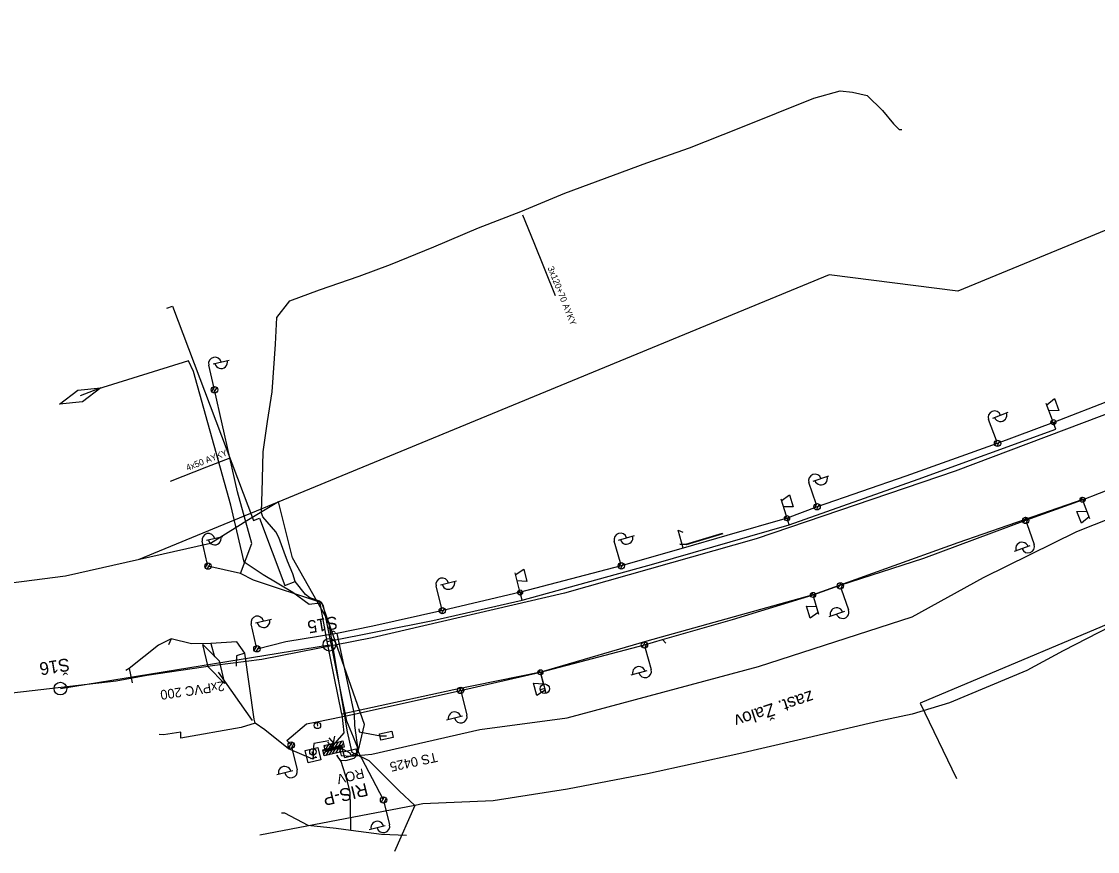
# Model space of a CAD drawing. Extents: x -748507 to -687366, y -1057342 to -1024924.
# Drawn here: x -745681.2 to -745512.4, y -1033626.6 to -1033496.4 of the extents above; entities that cross this region are included whole.
import ezdxf

# ---------------------------------------------------------------- set-up
doc = ezdxf.new("R2010")
doc.units = 0
for name, color, linetype in [('6kV - SŽDC', 7, 'Continuous'), ('DK + TKK - SŽDC', 7, 'Continuous'), ('DK - Pha Holešovice - Kralupy - ČD TELEMATIKA', 7, 'Continuous'), ('kanalizace ČD', 7, 'Continuous'), ('PRE - NN', 7, 'Continuous'), ('Sděl MK - SŽDC', 7, 'Continuous'), ('Telefonica O2', 7, 'Continuous'), ('TK+DOK_Pha Holešovice - Kralupy', 7, 'Continuous'), ('Vedení NN - SŽDC', 7, 'Continuous'), ('Vrstva 14', 7, 'Continuous')]:
    doc.layers.add(name, color=color, linetype=linetype)

msp = doc.modelspace()

# ---------------------------------------------------------------- linework, layer by layer
at = {"layer": '6kV - SŽDC'}
msp.add_lwpolyline([(-745623.06, -1033607.71), (-745622.85, -1033608.69), (-745624.8, -1033609.11), (-745625.01, -1033608.13), (-745623.06, -1033607.71)], dxfattribs=at)
at = {"layer": 'DK + TKK - SŽDC'}
for p, q in [((-745635.5, -1033610.94), (-745635.4, -1033610.94)), ((-745635.45, -1033610.94), (-745635.35, -1033611.47))]:
    msp.add_line(p, q, dxfattribs=at)
for points in [[(-745400.08, -1033513.57), (-745427.68, -1033524.27), (-745452.16, -1033534.47), (-745459.47, -1033537.75), (-745479.21, -1033545.61), (-745485.05, -1033547.78), (-745506.18, -1033556.13), (-745534.69, -1033566.93), (-745565.92, -1033577.52), (-745596.01, -1033586.03), (-745626.14, -1033593.03), (-745643.48, -1033596.47), (-745650.81, -1033597.4), (-745661.52, -1033598.96), (-745666.31, -1033599.86), (-745684.01, -1033601.91)], [(-745646.14, -1033595.44), (-745647.37, -1033593.68), (-745651.44, -1033593.92), (-745654.47, -1033593.99), (-745657.67, -1033593.23), (-745659.67, -1033594.21), (-745664.26, -1033597.87), (-745664.79, -1033598.17)], [(-745657.67, -1033593.23), (-745658.09, -1033594.14)], [(-745651.44, -1033593.92), (-745650.87, -1033596.04)], [(-745647.42, -1033595.9), (-745647.5, -1033597.52)], [(-745646.14, -1033595.44), (-745647.42, -1033595.9)], [(-745644.52, -1033606.43), (-745644.64, -1033605.81), (-745646.14, -1033595.44)], [(-745664.26, -1033597.87), (-745663.78, -1033600.09)], [(-745635.46, -1033612.08), (-745639.27, -1033610.46), (-745643, -1033607.49), (-745644.52, -1033606.43), (-745646.7, -1033607.11), (-745656.14, -1033608.79), (-745656.17, -1033607.85), (-745658.89, -1033608.26), (-745659.58, -1033608.2)], [(-745635.35, -1033611.47), (-745635.46, -1033612.08), (-745634.97, -1033611.67)]]:
    msp.add_lwpolyline(points, dxfattribs=at)
msp.add_circle((-745635.45, -1033610.94), 0.5, dxfattribs=at)
at = {"layer": 'DK - Pha Holešovice - Kralupy - ČD TELEMATIKA'}
msp.add_lwpolyline([(-745431.67, -1033496.38), (-745534.27, -1033538.65), (-745554.49, -1033536.11), (-745662.86, -1033580.81)], dxfattribs=at)
at = {"layer": 'kanalizace ČD'}
for p, q in [((-745576.95, -1033578.35), (-745571.2, -1033576.65)), ((-745577.91, -1033578.29), (-745576.95, -1033578.35))]:
    msp.add_line(p, q, dxfattribs=at)
for points in [[(-745571.15, -1033576.76), (-745576.92, -1033578.47), (-745577.91, -1033578.41)], [(-745675.05, -1033601.01), (-745632.86, -1033594.14)]]:
    msp.add_lwpolyline(points, dxfattribs=at)
for centre in [(-745632.86, -1033594.14), (-745675.05, -1033601.01)]:
    msp.add_circle(centre, 1, dxfattribs=at)
at = {"layer": 'PRE - NN'}
for points in [[(-745638.23, -1033584.22), (-745638.24, -1033584.21), (-745638.58, -1033583), (-745639.44, -1033581.03), (-745639.96, -1033579.64), (-745640.79, -1033577.29), (-745641.28, -1033576.41), (-745643.29, -1033574.08), (-745643.49, -1033573.45), (-745643.44, -1033571.53), (-745643.4, -1033570.21), (-745643.24, -1033563.88), (-745642.59, -1033559.13), (-745641.83, -1033554.45), (-745641.32, -1033547.01), (-745641.13, -1033542.81), (-745639.06, -1033540.19), (-745634.41, -1033538.48), (-745628.2, -1033536.34), (-745623.3, -1033534.49), (-745616.47, -1033531.74), (-745609.47, -1033528.73), (-745602.84, -1033526.2), (-745595.91, -1033523.32), (-745588.31, -1033520.48), (-745583.08, -1033518.55), (-745576.4, -1033516.2), (-745568.58, -1033513.09), (-745556.86, -1033508.39), (-745552.77, -1033507.23), (-745550.83, -1033507.45), (-745548.5, -1033507.97), (-745546.13, -1033510.35), (-745544.39, -1033512.43), (-745543.52, -1033513.33), (-745543.1, -1033513.31)], [(-745602.59, -1033526.68), (-745600.79, -1033531.05), (-745597.46, -1033539.34)], [(-745658.36, -1033541.35), (-745657.46, -1033541.01), (-745644.77, -1033574.64), (-745643.83, -1033574.28), (-745639.85, -1033584.82), (-745638.24, -1033584.21)], [(-745657.81, -1033568.48), (-745652.08, -1033566.23), (-745648.44, -1033564.84)], [(-745631.64, -1033611.45), (-745631.49, -1033611.85), (-745631.13, -1033612.23), (-745630.29, -1033612.31), (-745628.98, -1033611.93), (-745628.73, -1033611.66), (-745628.5, -1033611.07), (-745628.46, -1033610.2), (-745629.07, -1033608.61), (-745630.13, -1033606.11), (-745633.81, -1033588.02), (-745634.11, -1033587.54), (-745634.41, -1033587.32), (-745635.93, -1033586.8), (-745636.62, -1033586.24), (-745638.23, -1033584.22)], [(-745629.52, -1033623.21), (-745629.49, -1033622.95), (-745629.56, -1033619.43), (-745629.6, -1033617.29), (-745630.02, -1033615.6), (-745631.01, -1033612.45), (-745631.72, -1033611.45)], [(-745640.4, -1033620.51), (-745639.9, -1033620.52), (-745636.24, -1033622.42), (-745631.78, -1033622.93), (-745629.52, -1033623.21)], [(-745629.52, -1033623.21), (-745624.71, -1033623.85), (-745620.75, -1033624.02)]]:
    msp.add_lwpolyline(points, dxfattribs=at)
at = {"layer": 'Sděl MK - SŽDC'}
for p, q in [((-745520.36, -1033556.52), (-745519.14, -1033555.53)), ((-745519.14, -1033555.53), (-745518.43, -1033557.4)), ((-745520.47, -1033556.24), (-745519.48, -1033558.86)), ((-745518.43, -1033557.4), (-745520.01, -1033557.46)), ((-745519.64, -1033559.46), (-745519.35, -1033558.83)), ((-745519.27, -1033559.62), (-745518.99, -1033559)), ((-745562.08, -1033571.25), (-745561.23, -1033573.92)), ((-745561.98, -1033571.54), (-745560.7, -1033570.61)), ((-745560.7, -1033570.61), (-745560.1, -1033572.52)), ((-745514.78, -1033571), (-745515.06, -1033571.62)), ((-745514.41, -1033571.16), (-745514.7, -1033571.79)), ((-745560.1, -1033572.52), (-745561.69, -1033572.49)), ((-745513.57, -1033574.37), (-745514.57, -1033571.76)), ((-745561.42, -1033574.51), (-745561.1, -1033573.89)), ((-745561.07, -1033574.69), (-745560.75, -1033574.08)), ((-745515.61, -1033573.22), (-745514.03, -1033573.16)), ((-745514.9, -1033575.09), (-745515.61, -1033573.22)), ((-745513.68, -1033574.09), (-745514.9, -1033575.09)), ((-745603.79, -1033582.86), (-745603.08, -1033585.56)), ((-745603.71, -1033583.15), (-745602.39, -1033582.28)), ((-745602.39, -1033582.28), (-745601.88, -1033584.22)), ((-745601.88, -1033584.22), (-745603.46, -1033584.12)), ((-745603.29, -1033586.15), (-745602.94, -1033585.55)), ((-745602.94, -1033586.34), (-745602.6, -1033585.75)), ((-745557.03, -1033585.92), (-745557.36, -1033586.52)), ((-745556.67, -1033586.11), (-745557.01, -1033586.72)), ((-745557.47, -1033589.99), (-745558.04, -1033588.07)), ((-745558.04, -1033588.07), (-745556.45, -1033588.13)), ((-745556.09, -1033589.38), (-745556.88, -1033586.7)), ((-745556.18, -1033589.09), (-745557.47, -1033589.99)), ((-745599.78, -1033598.05), (-745600.12, -1033598.64)), ((-745599.43, -1033598.25), (-745599.78, -1033598.85)), ((-745598.93, -1033601.54), (-745599.65, -1033598.83)), ((-745600.33, -1033602.11), (-745600.84, -1033600.18)), ((-745600.84, -1033600.18), (-745599.26, -1033600.28)), ((-745599.01, -1033601.25), (-745600.33, -1033602.11)), ((-745632.36, -1033611.27), (-745631.63, -1033610.06)), ((-745631.85, -1033611.14), (-745631.11, -1033609.93)), ((-745635.32, -1033611.93), (-745635.56, -1033610.96)), ((-745633.85, -1033610.82), (-745633.69, -1033610.56)), ((-745633.72, -1033611.34), (-745633.17, -1033610.43)), ((-745633.39, -1033611.52), (-745632.66, -1033610.31)), ((-745632.88, -1033611.39), (-745632.14, -1033610.18)), ((-745631.33, -1033611.02), (-745630.89, -1033610.29)), ((-745630.82, -1033610.89), (-745630.77, -1033610.81)), ((-745634.84, -1033611.82), (-745635.81, -1033612.05))]:
    msp.add_line(p, q, dxfattribs=at)
for points in [[(-745633.23, -1033593.61), (-745634.32, -1033587.61), (-745636.06, -1033587.84), (-745638.61, -1033585.93), (-745643.25, -1033583.15), (-745646.23, -1033581.17), (-745648.31, -1033572.26), (-745654.16, -1033551.3), (-745654.98, -1033549.58), (-745669.24, -1033554.03), (-745671.95, -1033555.11)], [(-745668.7, -1033553.82), (-745671.58, -1033556.04), (-745675.2, -1033556.41), (-745672.33, -1033554.18), (-745668.7, -1033553.82)], [(-745518.94, -1033560.3), (-745519.32, -1033559.21)], [(-745630.92, -1033605.02), (-745632.09, -1033599.11), (-745633.23, -1033593.61), (-745616.65, -1033590.34), (-745602.63, -1033587.13), (-745581.95, -1033581.43), (-745560.76, -1033575.32), (-745540.52, -1033568.15), (-745518.94, -1033560.3)], [(-745514.7, -1033571.37), (-745534.28, -1033578.14), (-745556.98, -1033586.32), (-745583.06, -1033593.6), (-745599.72, -1033598.43), (-745613.34, -1033601.2), (-745630.92, -1033605.02), (-745630.61, -1033607.96), (-745632.67, -1033610.37)], [(-745560.76, -1033575.32), (-745561.07, -1033574.26)], [(-745602.63, -1033587.13), (-745602.93, -1033585.92)], [(-745652.7, -1033594.08), (-745650.13, -1033596.65), (-745649.3, -1033600.19), (-745651.87, -1033597.62), (-745652.7, -1033594.08)], [(-745644.92, -1033606.02), (-745650.28, -1033598.43)], [(-745632.95, -1033609.19), (-745635.29, -1033609.65), (-745635.44, -1033611.45)], [(-745633.9, -1033610.61), (-745630.99, -1033609.9), (-745630.75, -1033610.87), (-745633.66, -1033611.58), (-745633.9, -1033610.61)], [(-745633.16, -1033609.4), (-745632.44, -1033610.26), (-745632.19, -1033609.17)], [(-745634.23, -1033612.19), (-745636.18, -1033612.65), (-745636.65, -1033610.71), (-745634.7, -1033610.24), (-745634.23, -1033612.19)]]:
    msp.add_lwpolyline(points, dxfattribs=at)
msp.add_lwpolyline([(-745633.9, -1033610.61), (-745630.99, -1033609.9), (-745630.75, -1033610.87), (-745633.66, -1033611.58)], close=True, dxfattribs=at)
for centre in [(-745519.31, -1033559.22), (-745519.31, -1033559.22), (-745514.73, -1033571.39), (-745514.73, -1033571.39), (-745561.09, -1033574.29), (-745561.09, -1033574.29), (-745602.95, -1033585.94), (-745602.95, -1033585.94), (-745557.01, -1033586.32), (-745557.01, -1033586.32), (-745599.77, -1033598.45), (-745599.77, -1033598.45)]:
    msp.add_circle(centre, 0.401, dxfattribs=at)
at = {"layer": 'Telefonica O2'}
for points in [[(-745640.84, -1033571.74), (-745645.8, -1033574.71), (-745647.22, -1033575.58), (-745651.5, -1033578.23), (-745674.23, -1033583.39), (-745705.58, -1033587.39), (-745744.1, -1033592.23), (-745774.81, -1033594.04), (-745790.26, -1033593.55), (-745803.57, -1033589.22), (-745808.97, -1033585.37), (-745810.99, -1033582.68), (-745811.31, -1033577.67)], [(-745621.93, -1033617.07), (-745626.61, -1033612.37), (-745629.27, -1033611.04), (-745630.04, -1033607.82), (-745632.97, -1033590.57), (-745638.67, -1033580.52), (-745640.84, -1033571.74)], [(-745502.71, -1033587.52), (-745540.19, -1033603.31), (-745534.5, -1033615.11)], [(-745502.47, -1033589.3), (-745510.36, -1033591.27), (-745517.8, -1033595.11), (-745523.48, -1033598.16), (-745535.58, -1033603.24), (-745541.48, -1033605.02), (-745546.63, -1033606.1), (-745559.37, -1033609.12), (-745568.66, -1033611.24), (-745582.99, -1033614.39), (-745595.54, -1033616.77), (-745607.15, -1033618.64), (-745618.22, -1033619.09), (-745619.45, -1033619.36)], [(-745619.45, -1033619.36), (-745621.93, -1033617.07)], [(-745619.45, -1033619.36), (-745643.75, -1033623.98)], [(-745619.45, -1033619.36), (-745622.66, -1033626.57)]]:
    msp.add_lwpolyline(points, dxfattribs=at)
at = {"layer": 'TK+DOK_Pha Holešovice - Kralupy'}
msp.add_line((-745650.81, -1033597.4), (-745661.52, -1033598.96), dxfattribs=at)
for points in [[(-745467.39, -1033540.91), (-745474.77, -1033543.84), (-745485.05, -1033547.78), (-745506.18, -1033556.13), (-745534.69, -1033566.93), (-745565.92, -1033577.52), (-745596.01, -1033586.03), (-745626.14, -1033593.03), (-745643.48, -1033596.47), (-745650.81, -1033597.4), (-745661.52, -1033598.96), (-745666.31, -1033599.86), (-745684.01, -1033601.91)], [(-745485.05, -1033547.78), (-745506.18, -1033556.13), (-745534.69, -1033566.93), (-745565.92, -1033577.52), (-745596.01, -1033586.03), (-745626.14, -1033593.03), (-745643.48, -1033596.47), (-745650.81, -1033597.4), (-745661.52, -1033598.96), (-745666.31, -1033599.86), (-745684.01, -1033601.91)]]:
    msp.add_lwpolyline(points, dxfattribs=at)
at = {"layer": 'Vedení NN - SŽDC'}
for p, q in [((-745650.99, -1033553.66), (-745651.79, -1033550.26)), ((-745651.11, -1033550.09), (-745648.58, -1033549.5)), ((-745651.31, -1033554.4), (-745650.85, -1033553.65)), ((-745651.01, -1033554.63), (-745650.51, -1033553.82)), ((-745528.83, -1033558.57), (-745526.4, -1033557.65)), ((-745528.25, -1033562.09), (-745529.49, -1033558.81)), ((-745528.47, -1033562.86), (-745528.11, -1033562.06)), ((-745528.14, -1033563.05), (-745527.75, -1033562.18)), ((-745557, -1033568.48), (-745554.53, -1033567.64)), ((-745556.53, -1033572.02), (-745557.66, -1033568.71)), ((-745556.78, -1033572.78), (-745556.39, -1033571.99)), ((-745556.46, -1033572.98), (-745556.03, -1033572.12)), ((-745523.58, -1033574.15), (-745523.99, -1033575.01)), ((-745523.25, -1033574.34), (-745523.63, -1033575.14)), ((-745523.49, -1033575.11), (-745522.33, -1033578.41)), ((-745652.02, -1033581.32), (-745652.81, -1033577.91)), ((-745652.13, -1033577.75), (-745649.59, -1033577.17)), ((-745587.22, -1033581.28), (-745588.18, -1033577.91)), ((-745587.51, -1033577.72), (-745585.01, -1033577)), ((-745522.99, -1033578.64), (-745525.44, -1033579.51)), ((-745652.34, -1033582.05), (-745651.88, -1033581.31)), ((-745587.5, -1033582.03), (-745587.07, -1033581.26)), ((-745652.05, -1033582.28), (-745651.54, -1033581.47)), ((-745587.19, -1033582.24), (-745586.72, -1033581.41)), ((-745615.46, -1033584.74), (-745612.94, -1033584.1)), ((-745552.65, -1033584.41), (-745553.07, -1033585.27)), ((-745552.33, -1033584.61), (-745552.71, -1033585.4)), ((-745615.28, -1033588.31), (-745616.14, -1033584.92)), ((-745552.57, -1033585.38), (-745551.42, -1033588.68)), ((-745615.58, -1033589.05), (-745615.13, -1033588.3)), ((-745615.28, -1033589.28), (-745614.79, -1033588.45)), ((-745552.08, -1033588.91), (-745554.54, -1033589.76)), ((-745644.34, -1033594.29), (-745645.14, -1033590.88)), ((-745644.46, -1033590.72), (-745641.93, -1033590.13)), ((-745644.66, -1033595.03), (-745644.2, -1033594.28)), ((-745644.36, -1033595.25), (-745643.86, -1033594.44)), ((-745583.33, -1033593.69), (-745583.81, -1033594.53)), ((-745583.03, -1033593.91), (-745583.46, -1033594.68)), ((-745583.32, -1033594.66), (-745582.39, -1033598.04)), ((-745599.78, -1033598.06), (-745600.12, -1033598.64)), ((-745599.43, -1033598.25), (-745599.78, -1033598.85)), ((-745583.07, -1033598.22), (-745585.57, -1033598.91)), ((-745599.28, -1033600.31), (-745599.67, -1033598.84)), ((-745612.16, -1033600.81), (-745612.65, -1033601.64)), ((-745611.86, -1033601.04), (-745612.31, -1033601.79)), ((-745599.09, -1033601.01), (-745599.81, -1033601.2)), ((-745598.9, -1033601.74), (-745599.09, -1033601.01)), ((-745612.16, -1033601.78), (-745611.29, -1033605.17)), ((-745611.97, -1033605.34), (-745614.49, -1033605.99)), ((-745634.79, -1033606.8), (-745634.69, -1033606.8)), ((-745638.72, -1033609.41), (-745639.22, -1033610.22)), ((-745638.42, -1033609.64), (-745638.88, -1033610.39)), ((-745633.64, -1033610.15), (-745633.48, -1033609.89)), ((-745633.52, -1033610.67), (-745632.97, -1033609.76)), ((-745633.19, -1033610.84), (-745632.45, -1033609.64)), ((-745632.67, -1033610.72), (-745631.94, -1033609.51)), ((-745632.16, -1033610.59), (-745631.42, -1033609.39)), ((-745631.64, -1033610.47), (-745630.91, -1033609.26)), ((-745631.13, -1033610.34), (-745630.69, -1033609.62)), ((-745638.73, -1033610.38), (-745637.92, -1033613.78)), ((-745630.61, -1033610.22), (-745630.56, -1033610.13)), ((-745638.6, -1033613.94), (-745641.13, -1033614.55)), ((-745624.25, -1033618), (-745624.74, -1033618.82)), ((-745623.95, -1033618.23), (-745624.4, -1033618.98)), ((-745624.26, -1033618.97), (-745623.42, -1033622.37)), ((-745624.1, -1033622.53), (-745626.62, -1033623.16))]:
    msp.add_line(p, q, dxfattribs=at)
for points in [[(-745631.39, -1033610.02), (-745631, -1033611.52), (-745629.52, -1033611.59), (-745626.19, -1033611.31), (-745609.27, -1033607.45), (-745595.55, -1033605.58), (-745565.58, -1033597.57), (-745541.45, -1033589.74), (-745530.27, -1033583.57), (-745515.64, -1033576.36), (-745507.34, -1033573.1), (-745494.01, -1033566.15), (-745486.92, -1033560.08), (-745473.73, -1033555.55), (-745448.37, -1033544.19), (-745425.45, -1033535.39), (-745418.84, -1033532.6), (-745415.14, -1033534.73), (-745407.96, -1033532.2), (-745405.1, -1033530.37), (-745395.48, -1033525.68), (-745387.25, -1033522.76), (-745371.53, -1033515.62)], [(-745497.15, -1033550.57), (-745510.14, -1033555.7), (-745519.3, -1033559.25), (-745528.1, -1033562.56), (-745542.47, -1033567.67), (-745556.38, -1033572.5), (-745561.06, -1033574.29), (-745570.54, -1033577.02), (-745577.36, -1033578.97), (-745578.17, -1033576.16), (-745577.44, -1033576.49)], [(-745646.83, -1033582.98), (-745645.02, -1033578.27), (-745647.25, -1033570.15), (-745650.88, -1033554.15)], [(-745580.64, -1033593.33), (-745569.66, -1033590.2), (-745557.01, -1033586.31), (-745552.77, -1033584.8), (-745539.64, -1033580.55), (-745523.65, -1033574.61), (-745514.74, -1033571.39), (-745504.07, -1033567.23), (-745492.3, -1033562.57)], [(-745577.36, -1033578.97), (-745587.08, -1033581.76), (-745602.88, -1033585.88), (-745615.06, -1033588.78), (-745626.04, -1033591.22), (-745631.72, -1033592.35), (-745639.67, -1033593.69), (-745644.17, -1033594.83)], [(-745624.37, -1033618.48), (-745628.37, -1033610.88), (-745627.35, -1033606.65), (-745634.04, -1033587.58), (-745644.78, -1033583.99), (-745646.83, -1033582.98), (-745651.91, -1033581.8)], [(-745631.72, -1033592.35), (-745629, -1033605.02), (-745628.9, -1033606.8), (-745628.36, -1033610.99), (-745629.46, -1033611.49), (-745629.59, -1033611.16), (-745631.46, -1033610.17)], [(-745629, -1033605.02), (-745612.3, -1033601.3), (-745599.75, -1033598.46), (-745583.45, -1033594.15), (-745580.64, -1033593.33), (-745580.08, -1033593.87)], [(-745638.82, -1033609.9), (-745639.54, -1033609.14), (-745636.44, -1033606.53), (-745634.85, -1033606.23), (-745629, -1033605.02)], [(-745634.85, -1033606.23), (-745634.74, -1033606.8)], [(-745628.26, -1033607.35), (-745628.2, -1033607.78), (-745624.84, -1033608.43), (-745623.93, -1033608.41)], [(-745633.7, -1033609.94), (-745630.78, -1033609.23), (-745630.54, -1033610.2), (-745633.46, -1033610.91), (-745633.7, -1033609.94)], [(-745632.96, -1033608.73), (-745632.24, -1033609.58), (-745631.99, -1033608.49)], [(-745628.74, -1033610.44), (-745628.5, -1033611.41), (-745630.44, -1033611.88), (-745630.68, -1033610.91), (-745628.74, -1033610.44)]]:
    msp.add_lwpolyline(points, dxfattribs=at)
msp.add_lwpolyline([(-745633.7, -1033609.94), (-745630.78, -1033609.23), (-745630.54, -1033610.2), (-745633.46, -1033610.91)], close=True, dxfattribs=at)
for centre, radius in [((-745650.88, -1033554.15), 0.5), ((-745650.88, -1033554.15), 0.5), ((-745528.07, -1033562.55), 0.5), ((-745528.07, -1033562.55), 0.5), ((-745556.37, -1033572.49), 0.5), ((-745556.37, -1033572.49), 0.5), ((-745523.66, -1033574.64), 0.5), ((-745523.66, -1033574.64), 0.5), ((-745651.91, -1033581.8), 0.5), ((-745651.91, -1033581.8), 0.5), ((-745587.08, -1033581.76), 0.5), ((-745587.08, -1033581.76), 0.5), ((-745552.73, -1033584.9), 0.5), ((-745552.73, -1033584.9), 0.5), ((-745615.16, -1033588.79), 0.5), ((-745615.16, -1033588.79), 0.5), ((-745644.23, -1033594.77), 0.5), ((-745644.23, -1033594.77), 0.5), ((-745583.45, -1033594.18), 0.5), ((-745583.45, -1033594.18), 0.5), ((-745599.77, -1033598.45), 0.4), ((-745599.77, -1033598.45), 0.4), ((-745612.29, -1033601.3), 0.5), ((-745612.29, -1033601.3), 0.5), ((-745599.09, -1033601.03), 0.738), ((-745634.74, -1033606.8), 0.5), ((-745638.85, -1033609.89), 0.5), ((-745638.85, -1033609.89), 0.5), ((-745624.37, -1033618.48), 0.5), ((-745624.37, -1033618.48), 0.5)]:
    msp.add_circle(centre, radius, dxfattribs=at)
for centre, start, end in [((-745650.82, -1033550.03), 13.2558, 193.2558), ((-745649.84, -1033549.81), 192.5533, 13.9584), ((-745528.55, -1033558.46), 20.6962, 200.6962), ((-745527.61, -1033558.12), 199.9936, 21.3988), ((-745556.71, -1033568.38), 18.7885, 198.7885), ((-745555.76, -1033568.07), 198.086, 19.4911), ((-745651.83, -1033577.68), 12.9779, 192.9779), ((-745650.86, -1033577.47), 192.2754, 13.6805), ((-745587.22, -1033577.64), 16.0368, 196.0368), ((-745586.26, -1033577.37), 195.3343, 16.7394), ((-745524.22, -1033579.06), 18.7119, 200.1171), ((-745523.27, -1033578.74), 199.4145, 19.4145), ((-745615.17, -1033584.67), 14.2599, 194.2599), ((-745614.2, -1033584.44), 193.5573, 14.9625), ((-745644.17, -1033590.65), 13.1491, 193.1491), ((-745553.32, -1033589.33), 18.4223, 199.8275), ((-745552.37, -1033589.01), 199.1249, 19.1249), ((-745643.19, -1033590.44), 192.4465, 13.8516), ((-745584.32, -1033598.55), 14.6417, 196.0468), ((-745583.35, -1033598.3), 195.3443, 15.3443), ((-745613.23, -1033605.66), 13.6513, 195.0565), ((-745612.26, -1033605.42), 194.3539, 14.3539), ((-745639.87, -1033614.23), 12.723, 194.1282), ((-745638.89, -1033614.01), 193.4256, 13.4256), ((-745625.36, -1033622.83), 13.1228, 194.5279), ((-745624.39, -1033622.61), 193.8254, 13.8254)]:
    msp.add_arc(centre, 1, start, end, dxfattribs=at)

# ---------------------------------------------------------------- texts
at = {"layer": '6kV - SŽDC'}
msp.add_text('TS 0425', height=1.5, rotation=192.1649, dxfattribs=at).set_placement((-745616.1, -1033611.01))
at = {"layer": 'kanalizace ČD'}
for s, p in [('Š15', (-745631.74, -1033589.64)), ('Š16', (-745673.77, -1033596.22))]:
    msp.add_text(s, height=2, rotation=189.2391, dxfattribs=at).set_placement(p)
at = {"layer": 'PRE - NN'}
for s, rotation, p in [('3x120+70 AYKY', 291.8863, (-745598.66, -1033535.01)), ('4x50 AYKY', 21.4308, (-745655.13, -1033566.89))]:
    msp.add_text(s, height=1, rotation=rotation, dxfattribs=at).set_placement(p)
at = {"layer": 'TK+DOK_Pha Holešovice - Kralupy'}
msp.add_text('2xPVC 200', height=1.5, rotation=188.2904, dxfattribs=at).set_placement((-745649.43, -1033599.84))
at = {"layer": 'Vedení NN - SŽDC'}
for s, height, rotation, p in [('ROV', 1.5, 193.7152, (-745627.61, -1033613.53)), ('RIS-P', 2, 193.6419, (-745627.1, -1033615.81))]:
    msp.add_text(s, height=height, rotation=rotation, dxfattribs=at).set_placement(p)
at = {"layer": 'Vrstva 14'}
msp.add_text('zast. Žalov', height=2, rotation=198.097, dxfattribs=at).set_placement((-745557.29, -1033601.26))

doc.saveas('drawing.dxf')
